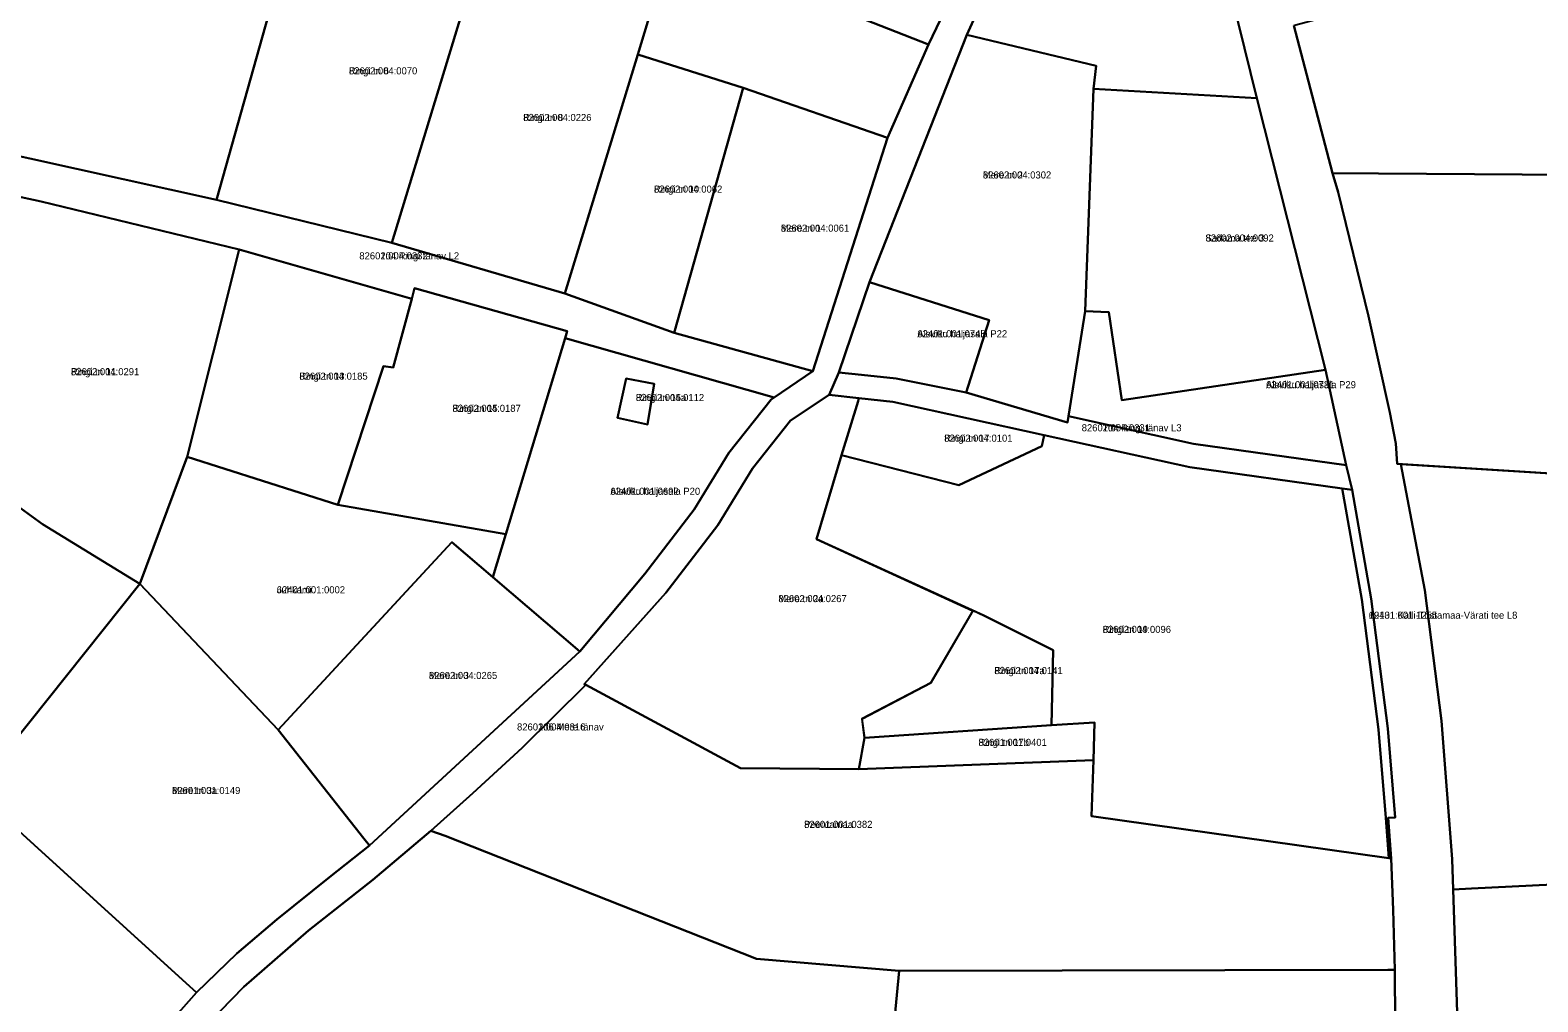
# Model space of a CAD drawing. Extents: x 491424 to 557740, y 6448618 to 6487207.
# Drawn here: x 499448.5 to 499768.6, y 6465645.2 to 6465851.5 of the extents above; entities that cross this region are included whole.
import ezdxf

# ---------------------------------------------------------------- set-up
doc = ezdxf.new("R2010")
doc.units = 0
for name, color, linetype in [('L_AADRESS', 7, 'Continuous'), ('PIIR', 7, 'Continuous'), ('TUNNUS', 7, 'Continuous')]:
    doc.layers.add(name, color=color, linetype=linetype)

msp = doc.modelspace()

# ---------------------------------------------------------------- linework, layer by layer
at = {"layer": 'PIIR'}
for points in [[(499120.19, 6466052.86), (499233.92, 6465955.28), (499335.7, 6465867.96), (499377.22, 6465855.34), (499377.71, 6465855.19), (499371.63, 6465833.43), (499371.4, 6465832.77), (499370.85, 6465830.89), (499364.52, 6465808.78), (499362.29, 6465803.18), (499421.53, 6465768.16), (499451.16, 6465746.68), (499471.8, 6465734.02), (499436.73, 6465690.03), (499481.63, 6465649.24), (499483.85, 6465647.22), (499475.69, 6465638.02)], [(499738.47, 6465607.17), (499738.18, 6465652.08), (499737.85, 6465664.76), (499737.43, 6465675.7), (499736.8, 6465684.32), (499738.29, 6465684.39), (499736.73, 6465703.28), (499733.2, 6465730.84), (499729.13, 6465753.92), (499727.85, 6465759.15), (499723.52, 6465779.44), (499708.94, 6465837.09), (499691.8, 6465906.56)], [(499670.58, 6465901.67), (499647.36, 6465850.54), (499626.72, 6465798.02), (499620.21, 6465778.82), (499618.12, 6465774.11), (499609.95, 6465768.67), (499601.85, 6465758.46), (499594.47, 6465746.46), (499583.49, 6465732.11), (499566.1, 6465712.68), (499566.49, 6465712.52), (499552.97, 6465699.17), (499542.53, 6465689.56), (499533.62, 6465681.58), (499521.25, 6465671.17), (499507.6, 6465660.43), (499493.91, 6465648.45), (499488.85, 6465643.28)], [(499475.69, 6465638.02), (499483.85, 6465647.22), (499492.42, 6465655.49), (499500.89, 6465662.76), (499512.08, 6465671.71), (499520.57, 6465678.42), (499565.18, 6465719.6), (499578.98, 6465736.08), (499589.45, 6465749.76), (499596.87, 6465761.82), (499605.85, 6465773.15), (499606.44, 6465773.55), (499614.69, 6465779.12), (499630.53, 6465828.65), (499639.23, 6465848.46), (499661.25, 6465894.43)], [(499716.74, 6465852.52), (499719.89, 6465840.63), (499724.98, 6465821.16), (499726.19, 6465817.15), (499732.61, 6465790.79), (499737.16, 6465770.37), (499738.44, 6465763.79), (499738.71, 6465759.43), (499739.5, 6465759.38), (499744.56, 6465732.64), (499748.11, 6465704.92), (499750.4, 6465675.54), (499750.61, 6465669.12), (499751.43, 6465642.97)], [(499488.85, 6465643.28), (499493.91, 6465648.45), (499507.6, 6465660.43), (499521.25, 6465671.17), (499533.62, 6465681.58), (499536.61, 6465680.5), (499602.72, 6465654.35), (499632.99, 6465651.84), (499629.28, 6465613.38)], [(499819.86, 6465604.47), (499751.54, 6465597.96), (499750.65, 6465597.89), (499751.71, 6465619.81), (499751.43, 6465642.97), (499750.61, 6465669.12), (499754.5, 6465669.31), (499794.76, 6465671.28)]]:
    msp.add_lwpolyline(points, dxfattribs=at)
for points in [[(499716.74, 6465852.52), (499717.16, 6465852.63), (499776.41, 6465868.6), (499768.06, 6465896.31), (499817.08, 6465896.71), (499823.35, 6465924.54), (499834.79, 6465922.31), (499871.35, 6465971.68), (499871.89, 6465972.41), (499884.79, 6465968.71), (499892.09, 6465966.48), (499891.86, 6465965.63), (499887.53, 6465949.17), (499886.14, 6465930.95), (499878.67, 6465916.45), (499870.44, 6465911.84), (499864.02, 6465866.23), (499857.4, 6465820.35), (499848.86, 6465820.4), (499846.67, 6465820.33), (499734.75, 6465821.09), (499724.98, 6465821.16), (499719.89, 6465840.63)], [(499458.29, 6465955.73), (499467.34, 6465953.38), (499452.29, 6465901.06), (499449.67, 6465894.06), (499433.45, 6465837.68), (499438.47, 6465826.48), (499488.1, 6465815.52), (499525.32, 6465806.37), (499562.05, 6465795.59), (499585.26, 6465787.29), (499614.69, 6465779.12), (499606.44, 6465773.55), (499562.1, 6465786.17), (499562.54, 6465787.64), (499530.12, 6465796.73), (499529.52, 6465794.51), (499492.87, 6465804.94), (499450.85, 6465815.12), (499438.09, 6465817.92), (499422.13, 6465821.45), (499443.72, 6465899), (499446.68, 6465910.71)], [(499620.08, 6465898.36), (499626.29, 6465910.99), (499657.96, 6465901.72), (499661.25, 6465894.43), (499639.23, 6465848.46), (499612.12, 6465859.16)], [(499691.8, 6465906.56), (499708.94, 6465837.09), (499674.22, 6465839.06), (499674.83, 6465843.95), (499647.36, 6465850.54), (499670.58, 6465901.67)], [(499452.29, 6465901.06), (499472.73, 6465895.37), (499511.01, 6465885.86), (499540.6, 6465878.53), (499582.15, 6465870.38), (499612.12, 6465859.16), (499639.23, 6465848.46), (499630.53, 6465828.65), (499599.86, 6465839.28), (499577.49, 6465846.35), (499581.06, 6465858.1), (499544.33, 6465868.88), (499505.73, 6465878.21), (499449.67, 6465894.06)], [(499433.45, 6465837.68), (499449.67, 6465894.06), (499505.73, 6465878.21), (499488.1, 6465815.52), (499438.47, 6465826.48)], [(499505.73, 6465878.21), (499544.33, 6465868.88), (499525.32, 6465806.37), (499488.1, 6465815.52)], [(499544.33, 6465868.88), (499581.06, 6465858.1), (499577.49, 6465846.35), (499562.05, 6465795.59), (499525.32, 6465806.37)], [(499674.83, 6465843.95), (499674.22, 6465839.06), (499672.49, 6465791.89), (499668.7, 6465768.26), (499647.2, 6465774.64), (499652.1, 6465789.94), (499626.72, 6465798.02), (499647.36, 6465850.54)], [(499577.49, 6465846.35), (499599.86, 6465839.28), (499585.26, 6465787.29), (499562.05, 6465795.59)], [(499599.86, 6465839.28), (499630.53, 6465828.65), (499614.69, 6465779.12), (499585.26, 6465787.29)], [(499672.49, 6465791.89), (499674.22, 6465839.06), (499708.94, 6465837.09), (499723.52, 6465779.44), (499680.28, 6465772.95), (499677.47, 6465791.65)], [(499734.75, 6465821.09), (499846.67, 6465820.33), (499848.86, 6465820.4), (499848.02, 6465815), (499849.34, 6465812.79), (499851.11, 6465809.83), (499854.68, 6465807.47), (499859.35, 6465806.16), (499866.56, 6465804.43), (499868.73, 6465802.91), (499869.79, 6465798.54), (499869.61, 6465795.93), (499868.68, 6465787.82), (499865.72, 6465788.06), (499823.07, 6465789.47), (499822.47, 6465755.37), (499798.66, 6465755.73), (499738.71, 6465759.43), (499738.44, 6465763.79), (499737.16, 6465770.37), (499732.61, 6465790.79), (499726.19, 6465817.15), (499724.98, 6465821.16)], [(499450.85, 6465815.12), (499492.87, 6465804.94), (499481.84, 6465760.93), (499471.8, 6465734.02), (499451.16, 6465746.68), (499421.53, 6465768.16), (499437.44, 6465815.97), (499438.09, 6465817.92)], [(499492.87, 6465804.94), (499529.52, 6465794.51), (499525.58, 6465779.88), (499523.54, 6465780.2), (499513.83, 6465750.79), (499481.84, 6465760.93)], [(499626.72, 6465798.02), (499652.1, 6465789.94), (499647.2, 6465774.64), (499632.38, 6465777.6), (499624.98, 6465778.38), (499620.21, 6465778.82)], [(499529.52, 6465794.51), (499530.12, 6465796.73), (499562.54, 6465787.64), (499562.1, 6465786.17), (499549.49, 6465744.55), (499513.83, 6465750.79), (499523.54, 6465780.2), (499525.58, 6465779.88)], [(499672.49, 6465791.89), (499677.47, 6465791.65), (499680.28, 6465772.95), (499723.52, 6465779.44), (499727.85, 6465759.15), (499695.46, 6465763.71), (499668.91, 6465769.55)], [(499562.1, 6465786.17), (499606.44, 6465773.55), (499605.85, 6465773.15), (499596.87, 6465761.82), (499589.45, 6465749.76), (499578.98, 6465736.08), (499565.18, 6465719.6), (499546.74, 6465735.38), (499549.49, 6465744.55)], [(499618.12, 6465774.11), (499620.21, 6465778.82), (499624.98, 6465778.38), (499632.38, 6465777.6), (499647.2, 6465774.64), (499668.7, 6465768.26), (499668.91, 6465769.55), (499695.46, 6465763.71), (499727.85, 6465759.15), (499729.13, 6465753.92), (499727.04, 6465754.21), (499694.72, 6465758.76), (499663.79, 6465765.56), (499631.66, 6465772.64), (499624.46, 6465773.4)], [(499580.97, 6465776.48), (499579.56, 6465767.81), (499573.23, 6465769.23), (499575.04, 6465777.61)], [(499575.04, 6465777.61), (499573.23, 6465769.23), (499579.56, 6465767.81), (499580.97, 6465776.48)], [(499624.46, 6465773.4), (499624.26, 6465772.78), (499620.72, 6465761.28), (499615.45, 6465743.5), (499648.62, 6465728.29), (499639.73, 6465712.98), (499625.1, 6465705.33), (499625.66, 6465701.3), (499624.41, 6465694.64), (499599.28, 6465694.88), (499566.49, 6465712.52), (499566.1, 6465712.68), (499583.49, 6465732.11), (499594.47, 6465746.46), (499601.85, 6465758.46), (499609.95, 6465768.67), (499618.12, 6465774.11)], [(499624.26, 6465772.78), (499624.46, 6465773.4), (499631.66, 6465772.64), (499663.79, 6465765.56), (499663.27, 6465763.19), (499645.68, 6465754.93), (499620.72, 6465761.28)], [(499736.93, 6465675.77), (499673.85, 6465684.64), (499674.22, 6465696.54), (499674.48, 6465704.54), (499665.34, 6465704.01), (499665.71, 6465719.89), (499650.94, 6465727.29), (499615.45, 6465743.5), (499620.72, 6465761.28), (499645.68, 6465754.93), (499663.27, 6465763.19), (499663.79, 6465765.56), (499694.72, 6465758.76), (499727.04, 6465754.21), (499731.21, 6465730.65), (499734.74, 6465703.09), (499736.3, 6465684.3)], [(499471.8, 6465734.02), (499481.84, 6465760.93), (499513.83, 6465750.79), (499549.49, 6465744.55), (499546.74, 6465735.38), (499538.07, 6465742.81), (499501.17, 6465703.03)], [(499739.5, 6465759.38), (499798.61, 6465755.73), (499790.64, 6465703.2), (499794.76, 6465671.28), (499754.5, 6465669.31), (499750.61, 6465669.12), (499750.4, 6465675.54), (499748.11, 6465704.92), (499744.56, 6465732.64)], [(499736.73, 6465703.28), (499738.29, 6465684.39), (499736.8, 6465684.32), (499737.43, 6465675.7), (499736.93, 6465675.77), (499736.3, 6465684.3), (499734.74, 6465703.09), (499731.21, 6465730.65), (499727.04, 6465754.21), (499729.13, 6465753.92), (499733.2, 6465730.84)], [(499501.17, 6465703.03), (499538.07, 6465742.81), (499546.74, 6465735.38), (499565.18, 6465719.6), (499520.57, 6465678.42), (499519.35, 6465679.95)], [(499436.73, 6465690.03), (499471.8, 6465734.02), (499501.17, 6465703.03), (499519.35, 6465679.95), (499520.57, 6465678.42), (499512.08, 6465671.71), (499500.89, 6465662.76), (499492.42, 6465655.49), (499483.85, 6465647.22), (499481.63, 6465649.24)], [(499665.34, 6465704.01), (499625.66, 6465701.3), (499625.11, 6465705.34), (499639.75, 6465712.98), (499648.67, 6465728.33), (499650.94, 6465727.29), (499665.71, 6465719.89)], [(499552.97, 6465699.17), (499566.49, 6465712.52), (499599.28, 6465694.88), (499624.41, 6465694.64), (499674.22, 6465696.54), (499673.85, 6465684.64), (499736.93, 6465675.77), (499737.43, 6465675.7), (499737.85, 6465664.76), (499738.18, 6465652.08), (499736.7, 6465652.08), (499632.99, 6465651.84), (499602.72, 6465654.35), (499536.61, 6465680.5), (499533.62, 6465681.58), (499542.53, 6465689.56)], [(499624.41, 6465694.64), (499625.66, 6465701.3), (499665.34, 6465704.01), (499674.48, 6465704.54), (499674.22, 6465696.54)], [(499738.18, 6465652.08), (499738.47, 6465607.17), (499686.65, 6465609.16), (499629.28, 6465613.38), (499632.99, 6465651.84), (499736.7, 6465652.08)]]:
    msp.add_lwpolyline(points, close=True, dxfattribs=at)

# ---------------------------------------------------------------- texts
at = {"layer": 'L_AADRESS'}
for s, p in [('Ringi tn 6', (499516.21, 6465842.14)), ('Ringi tn 8', (499553.19, 6465832.24)), ('Mere tn 2', (499650.77, 6465820.04)), ('Ringi tn 10', (499580.95, 6465817.04)), ('Mere tn 1', (499607.89, 6465808.75)), ('Sadama tee 3', (499698.01, 6465806.66)), ('8260104 Ringi tänav L2', (499518.41, 6465802.87)), ('Aleviku haljasala P22', (499636.85, 6465786.33)), ('Ringi tn 11', (499457.2, 6465778.28)), ('Ringi tn 13', (499505.68, 6465777.33)), ('Aleviku haljasala P29', (499710.88, 6465775.52)), ('Ringi tn 15', (499538.18, 6465770.5)), ('Ringi tn 15a', (499577.1, 6465772.79)), ('Ringi tn 17', (499642.55, 6465764.16)), ('8260104 Ringi tänav L3', (499671.74, 6465766.37)), ('Aleviku haljasala P20', (499571.69, 6465752.89)), ('Juhkami', (499500.88, 6465731.98)), ('Mere tn 2a', (499607.36, 6465730.1)), ('19131 Kalli-Tõstamaa-Värati tee L8', (499732.66, 6465726.58)), ('Ringi tn 19', (499676.19, 6465723.57)), ('Mere tn 3', (499533.18, 6465713.79)), ('Ringi tn 17a', (499653.2, 6465714.82)), ('8260106 Mere tänav', (499551.88, 6465702.86)), ('Ringi tn 17b', (499649.83, 6465699.59)), ('Mere tn 3a', (499478.65, 6465689.37)), ('Peenramaa', (499612.82, 6465682.18))]:
    msp.add_text(s, height=1.5, dxfattribs=at).set_placement(p)
at = {"layer": 'TUNNUS'}
for s, p in [('82602:004:0070', (499516.21, 6465842.14)), ('82602:004:0226', (499553.19, 6465832.24)), ('82602:004:0302', (499650.77, 6465820.04)), ('82602:004:0062', (499580.95, 6465817.04)), ('82602:004:0061', (499607.89, 6465808.75)), ('82602:004:0092', (499698.01, 6465806.66)), ('82602:004:0332', (499518.41, 6465802.87)), ('62401:001:0748', (499636.85, 6465786.33)), ('82602:004:0291', (499457.2, 6465778.28)), ('82602:004:0185', (499505.68, 6465777.33)), ('62401:001:0731', (499710.88, 6465775.52)), ('82602:004:0187', (499538.18, 6465770.5)), ('82602:004:0112', (499577.1, 6465772.79)), ('82602:004:0101', (499642.55, 6465764.16)), ('82602:004:0331', (499671.74, 6465766.37)), ('62401:001:0692', (499571.69, 6465752.89)), ('62401:001:0002', (499500.88, 6465731.98)), ('82602:004:0267', (499607.36, 6465730.1)), ('62401:001:1255', (499732.66, 6465726.58)), ('82602:004:0096', (499676.19, 6465723.57)), ('82602:004:0265', (499533.18, 6465713.79)), ('82602:004:0141', (499653.2, 6465714.82)), ('82602:004:0316', (499551.88, 6465702.86)), ('82601:001:0401', (499649.83, 6465699.59)), ('82601:001:0149', (499478.65, 6465689.37)), ('82601:001:0382', (499612.82, 6465682.18))]:
    msp.add_text(s, height=1.5, dxfattribs=at).set_placement(p)

doc.saveas('drawing.dxf')
